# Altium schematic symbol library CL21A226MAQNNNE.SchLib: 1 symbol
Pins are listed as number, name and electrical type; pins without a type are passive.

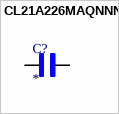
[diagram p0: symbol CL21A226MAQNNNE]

## CL21A226MAQNNNE
designator C?
MF: {'manufacturer': u'Samsung Electro-Mechanics'}; MP: CL21A226MAQNNNE
footprint CAPC2012X140N
pins: 1, 2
